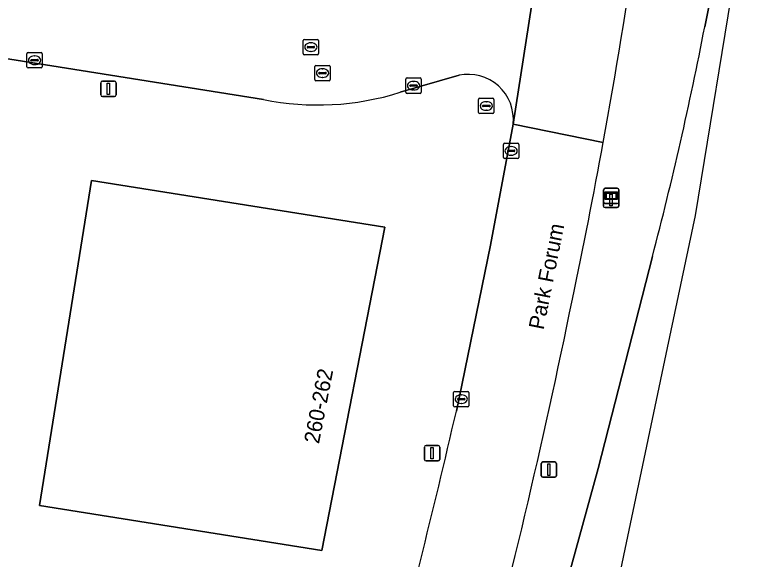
# Model space of a CAD drawing. Extents: x 154324 to 155744, y 382937 to 384188.
# Drawn here: x 155344.13 to 155393.14, y 383264.28 to 383299.76 of the extents above; entities that cross this region are included whole.
import ezdxf

# ---------------------------------------------------------------- set-up
doc = ezdxf.new("R2010")
doc.units = 0
for name, color, linetype in [('IMGEO_Berm_groen', 7, 'Continuous'), ('IMGEO_Brandkraan', 7, 'Continuous'), ('IMGEO_Erf', 7, 'Continuous'), ('IMGEO_Fietspad_gesloten', 7, 'Continuous'), ('IMGEO_Kolk', 7, 'Continuous'), ('IMGEO_Lichtmast', 7, 'Continuous'), ('IMGEO_Openbare_ruimte_label', 7, 'Continuous'), ('IMGEO_Pand', 7, 'Continuous'), ('IMGEO_Pand_nummerreeks', 7, 'Continuous'), ('IMGEO_Rijbaan_lokaal_gesloten', 7, 'Continuous'), ('IMGEO_Rijbaan_lokaal_open', 7, 'Continuous'), ('IMGEO_Rioolput', 7, 'Continuous'), ('IMGEO_Verklikker', 7, 'Continuous')]:
    doc.layers.add(name, color=color, linetype=linetype)

msp = doc.modelspace()

# ---------------------------------------------------------------- linework, layer by layer
at = {"layer": 'IMGEO_Berm_groen'}
for points in [[(155389.025, 383298.986), (155392.104, 383314.484)], [(155378.211, 383256.107), (155382.092, 383270.232), (155385.619, 383284.035)]]:
    msp.add_lwpolyline(points, dxfattribs=at)
for centre, radius, start, end in [((155001.57, 383361.032), 387.149, 349.64863, 353.73096), ((155162.148, 383342.808), 231.07, 345.26497, 349.06787), ((155004.637, 383360.399), 384.018, 348.10768, 349.65929), ((154920.161, 383375.05), 469.711, 344.96734, 348.48239)]:
    msp.add_arc(centre, radius, start, end, dxfattribs=at)
at = {"layer": 'IMGEO_Brandkraan'}
for p, q in [((155374.307, 383293.413), (155374.307, 383294.265)), ((155374.382, 383294.339), (155375.234, 383294.339)), ((155375.308, 383294.265), (155375.308, 383293.413)), ((155374.566, 383293.833), (155374.566, 383293.845)), ((155375.004, 383293.796), (155374.606, 383293.796)), ((155374.609, 383293.882), (155375.007, 383293.882)), ((155374.795, 383294.119), (155374.82, 383294.119)), ((155375.05, 383293.845), (155375.05, 383293.833)), ((155375.234, 383293.339), (155374.382, 383293.339)), ((155374.818, 383293.559), (155374.793, 383293.559))]:
    msp.add_line(p, q, dxfattribs=at)
for points in [[(155374.307, 383293.413), (155374.307, 383294.265)], [(155374.382, 383294.339), (155375.234, 383294.339)], [(155375.308, 383294.265), (155375.308, 383293.413)], [(155375.234, 383293.339), (155374.382, 383293.339)]]:
    msp.add_lwpolyline(points, dxfattribs=at)
for centre, radius, start, end in [((155374.384, 383294.263), 0.0765, 91.552, 178.448), ((155374.384, 383294.263), 0.0765, 91.552, 178.448), ((155375.232, 383294.263), 0.0765, 1.552, 88.448), ((155375.232, 383294.263), 0.0765, 1.552, 88.448), ((155374.606, 383293.842), 0.0403, 85.8775, 175.7526), ((155374.603, 383293.832), 0.0366, 178.938, 274.7102), ((155375.007, 383293.839), 0.043, 264.8664, 352.4533), ((155375.011, 383293.844), 0.0386, 1.7309, 96.639), ((155374.384, 383293.415), 0.0765, 181.552, 268.448), ((155374.384, 383293.415), 0.0765, 181.552, 268.448), ((155375.232, 383293.415), 0.0765, 271.552, 358.448), ((155375.232, 383293.415), 0.0765, 271.552, 358.448)]:
    msp.add_arc(centre, radius, start, end, dxfattribs=at)
for centre, major_axis, ratio, start_param, end_param in [((155374.794, 383293.839), (-0.387, 0.002), 0.722429, 4.712389, 7.853982), ((155374.819, 383293.839), (-0.39, 0.002), 0.717154, 1.570796, 4.712389)]:
    msp.add_ellipse(centre, major_axis=major_axis, ratio=ratio, start_param=start_param, end_param=end_param, dxfattribs=at)
at = {"layer": 'IMGEO_Erf'}
for points in [[(155360.296, 383294.263), (155341.319, 383297.286), (155334.487, 383253.554), (155331.676, 383253.994), (155326.27, 383221.771), (155342.552, 383219.211)], [(155373.032, 383295.835), (155369.195, 383294.73)], [(155372.858, 383273.968), (155375.091, 383284.785), (155376.559, 383292.665)]]:
    msp.add_lwpolyline(points, dxfattribs=at)
msp.add_lwpolyline([(155345.718, 383267.835), (155349.104, 383288.993), (155368.192, 383285.952), (155364.094, 383264.892)], close=True, dxfattribs=at)
for centre, radius, start, end in [((155373.627, 383292.95), 2.946, 354.4495, 101.6533), ((155363.845, 383311.656), 17.752, 258.4676, 287.5404), ((154771.317, 383413.289), 617.464, 345.099417, 346.959795)]:
    msp.add_arc(centre, radius, start, end, dxfattribs=at)
at = {"layer": 'IMGEO_Fietspad_gesloten'}
for points in [[(155374.508, 383231.879), (155378.906, 383245.985), (155381.726, 383255.864), (155383.313, 383262.405), (155386.611, 383278.083), (155388.426, 383286.714), (155391.127, 383303.306), (155393.141, 383320.278)], [(155392.104, 383314.484), (155389.025, 383298.986)], [(155385.619, 383284.035), (155382.092, 383270.232), (155378.211, 383256.107)]]:
    msp.add_lwpolyline(points, dxfattribs=at)
msp.add_arc((155162.148, 383342.808), 231.07, 345.26497, 349.06787, dxfattribs=at)
at = {"layer": 'IMGEO_Kolk'}
for p, q in [((155344.904, 383296.389), (155344.904, 383297.241)), ((155344.979, 383297.315), (155345.831, 383297.315)), ((155345.905, 383297.241), (155345.905, 383296.389)), ((155345.163, 383296.809), (155345.163, 383296.821)), ((155345.601, 383296.772), (155345.203, 383296.772)), ((155345.206, 383296.858), (155345.604, 383296.858)), ((155345.392, 383297.095), (155345.417, 383297.095)), ((155345.647, 383296.821), (155345.647, 383296.809)), ((155345.831, 383296.315), (155344.979, 383296.315)), ((155345.415, 383296.535), (155345.39, 383296.535)), ((155369.571, 383294.736), (155369.571, 383295.588)), ((155369.646, 383295.662), (155370.498, 383295.662)), ((155370.059, 383295.442), (155370.084, 383295.442)), ((155370.572, 383295.588), (155370.572, 383294.736)), ((155369.83, 383295.156), (155369.83, 383295.168)), ((155370.268, 383295.119), (155369.87, 383295.119)), ((155369.873, 383295.205), (155370.271, 383295.205)), ((155370.082, 383294.882), (155370.057, 383294.882)), ((155370.314, 383295.168), (155370.314, 383295.156)), ((155370.498, 383294.662), (155369.646, 383294.662)), ((155375.919, 383290.489), (155375.919, 383291.341)), ((155375.994, 383291.415), (155376.846, 383291.415)), ((155376.92, 383291.341), (155376.92, 383290.489)), ((155376.178, 383290.909), (155376.178, 383290.921)), ((155376.616, 383290.872), (155376.218, 383290.872)), ((155376.221, 383290.958), (155376.619, 383290.958)), ((155376.407, 383291.195), (155376.432, 383291.195)), ((155376.662, 383290.921), (155376.662, 383290.909)), ((155376.846, 383290.415), (155375.994, 383290.415)), ((155376.43, 383290.635), (155376.405, 383290.635)), ((155372.679, 383274.325), (155372.679, 383275.177)), ((155372.754, 383275.251), (155373.606, 383275.251)), ((155373.68, 383275.177), (155373.68, 383274.325)), ((155372.938, 383274.745), (155372.938, 383274.757)), ((155373.376, 383274.708), (155372.978, 383274.708)), ((155372.981, 383274.794), (155373.379, 383274.794)), ((155373.167, 383275.031), (155373.192, 383275.031)), ((155373.422, 383274.757), (155373.422, 383274.745)), ((155373.606, 383274.251), (155372.754, 383274.251)), ((155373.19, 383274.471), (155373.165, 383274.471))]:
    msp.add_line(p, q, dxfattribs=at)
for points in [[(155344.904, 383296.389), (155344.904, 383297.241)], [(155344.979, 383297.315), (155345.831, 383297.315)], [(155345.905, 383297.241), (155345.905, 383296.389)], [(155345.831, 383296.315), (155344.979, 383296.315)], [(155369.571, 383294.736), (155369.571, 383295.588)], [(155369.646, 383295.662), (155370.498, 383295.662)], [(155370.572, 383295.588), (155370.572, 383294.736)], [(155370.498, 383294.662), (155369.646, 383294.662)], [(155375.919, 383290.489), (155375.919, 383291.341)], [(155375.994, 383291.415), (155376.846, 383291.415)], [(155376.92, 383291.341), (155376.92, 383290.489)], [(155376.846, 383290.415), (155375.994, 383290.415)], [(155372.679, 383274.325), (155372.679, 383275.177)], [(155372.754, 383275.251), (155373.606, 383275.251)], [(155373.68, 383275.177), (155373.68, 383274.325)], [(155373.606, 383274.251), (155372.754, 383274.251)]]:
    msp.add_lwpolyline(points, dxfattribs=at)
for centre, radius, start, end in [((155344.981, 383297.239), 0.0765, 91.552, 178.448), ((155344.981, 383297.239), 0.0765, 91.552, 178.448), ((155345.829, 383297.239), 0.0765, 1.552, 88.448), ((155345.829, 383297.239), 0.0765, 1.552, 88.448), ((155345.203, 383296.818), 0.0403, 85.8775, 175.7526), ((155345.2, 383296.808), 0.0366, 178.938, 274.7102), ((155345.604, 383296.815), 0.043, 264.8664, 352.4533), ((155345.608, 383296.82), 0.0386, 1.7309, 96.639), ((155344.981, 383296.391), 0.0765, 181.552, 268.448), ((155344.981, 383296.391), 0.0765, 181.552, 268.448), ((155345.829, 383296.391), 0.0765, 271.552, 358.448), ((155345.829, 383296.391), 0.0765, 271.552, 358.448), ((155369.648, 383295.586), 0.0765, 91.552, 178.448), ((155369.648, 383295.586), 0.0765, 91.552, 178.448), ((155370.496, 383295.586), 0.0765, 1.552, 88.448), ((155370.496, 383295.586), 0.0765, 1.552, 88.448), ((155369.648, 383294.738), 0.0765, 181.552, 268.448), ((155369.648, 383294.738), 0.0765, 181.552, 268.448), ((155369.87, 383295.165), 0.0403, 85.8775, 175.7526), ((155369.867, 383295.155), 0.0366, 178.938, 274.7102), ((155370.271, 383295.162), 0.043, 264.8664, 352.4533), ((155370.275, 383295.167), 0.0386, 1.7309, 96.639), ((155370.496, 383294.738), 0.0765, 271.552, 358.448), ((155370.496, 383294.738), 0.0765, 271.552, 358.448), ((155375.996, 383291.339), 0.0765, 91.552, 178.448), ((155375.996, 383291.339), 0.0765, 91.552, 178.448), ((155376.844, 383291.339), 0.0765, 1.552, 88.448), ((155376.844, 383291.339), 0.0765, 1.552, 88.448), ((155376.218, 383290.918), 0.0403, 85.8775, 175.7526), ((155376.215, 383290.908), 0.0366, 178.938, 274.7102), ((155376.619, 383290.915), 0.043, 264.8664, 352.4533), ((155376.623, 383290.92), 0.0386, 1.7309, 96.639), ((155375.996, 383290.491), 0.0765, 181.552, 268.448), ((155375.996, 383290.491), 0.0765, 181.552, 268.448), ((155376.844, 383290.491), 0.0765, 271.552, 358.448), ((155376.844, 383290.491), 0.0765, 271.552, 358.448), ((155372.756, 383275.175), 0.0765, 91.552, 178.448), ((155372.756, 383275.175), 0.0765, 91.552, 178.448), ((155373.604, 383275.175), 0.0765, 1.552, 88.448), ((155373.604, 383275.175), 0.0765, 1.552, 88.448), ((155372.978, 383274.754), 0.0403, 85.8775, 175.7526), ((155372.975, 383274.744), 0.0366, 178.938, 274.7102), ((155373.379, 383274.751), 0.043, 264.8664, 352.4533), ((155373.383, 383274.756), 0.0386, 1.7309, 96.639), ((155372.756, 383274.327), 0.0765, 181.552, 268.448), ((155372.756, 383274.327), 0.0765, 181.552, 268.448), ((155373.604, 383274.327), 0.0765, 271.552, 358.448), ((155373.604, 383274.327), 0.0765, 271.552, 358.448)]:
    msp.add_arc(centre, radius, start, end, dxfattribs=at)
for centre, major_axis, ratio, start_param, end_param in [((155345.391, 383296.815), (-0.387, 0.002), 0.722429, 4.712389, 7.853982), ((155345.416, 383296.815), (-0.39, 0.002), 0.717154, 1.570796, 4.712389), ((155370.058, 383295.162), (-0.387, 0.002), 0.722429, 4.712389, 7.853982), ((155370.083, 383295.162), (-0.39, 0.002), 0.717154, 1.570796, 4.712389), ((155376.406, 383290.915), (-0.387, 0.002), 0.722429, 4.712389, 7.853982), ((155376.431, 383290.915), (-0.39, 0.002), 0.717154, 1.570796, 4.712389), ((155373.166, 383274.751), (-0.387, 0.002), 0.722429, 4.712389, 7.853982), ((155373.191, 383274.751), (-0.39, 0.002), 0.717154, 1.570796, 4.712389)]:
    msp.add_ellipse(centre, major_axis=major_axis, ratio=ratio, start_param=start_param, end_param=end_param, dxfattribs=at)
at = {"layer": 'IMGEO_Lichtmast'}
for p, q in [((155349.716, 383294.555), (155349.716, 383295.355)), ((155349.716, 383295.355), (155349.716, 383294.555)), ((155349.816, 383295.455), (155350.606, 383295.455)), ((155350.606, 383295.455), (155349.816, 383295.455)), ((155350.706, 383295.355), (155350.706, 383294.555)), ((155350.706, 383294.555), (155350.706, 383295.355)), ((155350.606, 383294.455), (155349.816, 383294.455)), ((155349.816, 383294.455), (155350.606, 383294.455)), ((155382.438, 383287.323), (155382.438, 383288.123)), ((155382.438, 383288.123), (155382.438, 383287.323)), ((155382.538, 383288.223), (155383.328, 383288.223)), ((155383.328, 383288.223), (155382.538, 383288.223)), ((155383.428, 383288.123), (155383.428, 383287.323)), ((155383.428, 383287.323), (155383.428, 383288.123)), ((155383.328, 383287.223), (155382.538, 383287.223)), ((155382.538, 383287.223), (155383.328, 383287.223)), ((155370.883, 383271.731), (155371.673, 383271.731)), ((155371.673, 383271.731), (155370.883, 383271.731)), ((155370.783, 383270.831), (155370.783, 383271.631)), ((155370.783, 383271.631), (155370.783, 383270.831)), ((155371.773, 383271.631), (155371.773, 383270.831)), ((155371.773, 383270.831), (155371.773, 383271.631)), ((155371.673, 383270.731), (155370.883, 383270.731)), ((155370.883, 383270.731), (155371.673, 383270.731)), ((155378.383, 383269.765), (155378.383, 383270.565)), ((155378.383, 383270.565), (155378.383, 383269.765)), ((155378.483, 383270.665), (155379.273, 383270.665)), ((155379.273, 383270.665), (155378.483, 383270.665)), ((155379.373, 383270.565), (155379.373, 383269.765)), ((155379.373, 383269.765), (155379.373, 383270.565)), ((155379.273, 383269.665), (155378.483, 383269.665)), ((155378.483, 383269.665), (155379.273, 383269.665))]:
    msp.add_line(p, q, dxfattribs=at)
for points in [[(155350.136, 383295.33), (155350.286, 383295.33), (155350.286, 383294.58), (155350.136, 383294.58), (155350.136, 383295.33)], [(155382.858, 383288.098), (155383.008, 383288.098), (155383.008, 383287.348), (155382.858, 383287.348), (155382.858, 383288.098)], [(155371.203, 383271.606), (155371.353, 383271.606), (155371.353, 383270.856), (155371.203, 383270.856), (155371.203, 383271.606)], [(155378.803, 383270.54), (155378.953, 383270.54), (155378.953, 383269.79), (155378.803, 383269.79), (155378.803, 383270.54)]]:
    msp.add_lwpolyline(points, dxfattribs=at)
for centre, start, end in [((155349.816, 383295.355), 90, 180), ((155349.816, 383295.355), 90, 180), ((155350.606, 383295.355), 0, 90), ((155350.606, 383295.355), 360, 90), ((155349.816, 383294.555), 180, 270), ((155349.816, 383294.555), 180, 270), ((155350.606, 383294.555), 270, 0), ((155350.606, 383294.555), 270, 0), ((155382.538, 383288.123), 90, 180), ((155382.538, 383288.123), 90, 180), ((155383.328, 383288.123), 0, 90), ((155383.328, 383288.123), 360, 90), ((155382.538, 383287.323), 180, 270), ((155382.538, 383287.323), 180, 270), ((155383.328, 383287.323), 270, 0), ((155383.328, 383287.323), 270, 0), ((155370.883, 383271.631), 90, 180), ((155370.883, 383271.631), 90, 180), ((155371.673, 383271.631), 0, 90), ((155371.673, 383271.631), 360, 90), ((155370.883, 383270.831), 180, 270), ((155370.883, 383270.831), 180, 270), ((155371.673, 383270.831), 270, 0), ((155371.673, 383270.831), 270, 0), ((155378.483, 383270.565), 90, 180), ((155378.483, 383270.565), 90, 180), ((155379.273, 383270.565), 0, 90), ((155379.273, 383270.565), 360, 90), ((155378.483, 383269.765), 180, 270), ((155378.483, 383269.765), 180, 270), ((155379.273, 383269.765), 270, 0), ((155379.273, 383269.765), 270, 0)]:
    msp.add_arc(centre, 0.1, start, end, dxfattribs=at)
at = {"layer": 'IMGEO_Pand'}
msp.add_lwpolyline([(155368.192, 383285.952), (155349.104, 383288.993), (155345.718, 383267.835), (155364.094, 383264.892)], close=True, dxfattribs=at)
at = {"layer": 'IMGEO_Rijbaan_lokaal_gesloten'}
msp.add_lwpolyline([(155382.418, 383291.467), (155376.559, 383292.665), (155375.091, 383284.785), (155372.858, 383273.968)], dxfattribs=at)
for centre, radius, start, end in [((155004.637, 383360.399), 384.018, 348.10768, 349.65929), ((154920.161, 383375.05), 469.711, 344.96734, 348.48239), ((154771.317, 383413.289), 617.464, 345.099417, 346.959795)]:
    msp.add_arc(centre, radius, start, end, dxfattribs=at)
at = {"layer": 'IMGEO_Rijbaan_lokaal_open'}
for points in [[(155214.765, 383317.447), (155341.319, 383297.286), (155360.296, 383294.263)], [(155379.953, 383314.794), (155379.78, 383313.49), (155376.559, 383292.665), (155382.418, 383291.467)], [(155376.559, 383292.665), (155379.78, 383313.49)], [(155369.195, 383294.73), (155373.032, 383295.835)]]:
    msp.add_lwpolyline(points, dxfattribs=at)
for centre, radius, start, end in [((155001.57, 383361.032), 387.149, 349.64863, 353.73096), ((155373.627, 383292.95), 2.946, 354.4495, 101.6533), ((155363.845, 383311.656), 17.752, 258.4676, 287.5404)]:
    msp.add_arc(centre, radius, start, end, dxfattribs=at)
at = {"layer": 'IMGEO_Rioolput'}
for p, q in [((155362.963, 383298.173), (155363.815, 383298.173)), ((155362.888, 383297.247), (155362.888, 383298.099)), ((155363.147, 383297.667), (155363.147, 383297.679)), ((155363.19, 383297.716), (155363.588, 383297.716)), ((155363.376, 383297.953), (155363.401, 383297.953)), ((155363.631, 383297.679), (155363.631, 383297.667)), ((155363.889, 383298.099), (155363.889, 383297.247)), ((155363.815, 383297.173), (155362.963, 383297.173)), ((155363.585, 383297.63), (155363.187, 383297.63)), ((155363.399, 383297.393), (155363.374, 383297.393)), ((155363.646, 383295.556), (155363.646, 383296.408)), ((155363.721, 383296.482), (155364.573, 383296.482)), ((155364.134, 383296.262), (155364.159, 383296.262)), ((155364.647, 383296.408), (155364.647, 383295.556)), ((155363.905, 383295.976), (155363.905, 383295.988)), ((155364.343, 383295.939), (155363.945, 383295.939)), ((155363.948, 383296.025), (155364.346, 383296.025)), ((155364.157, 383295.702), (155364.132, 383295.702)), ((155364.389, 383295.988), (155364.389, 383295.976)), ((155364.573, 383295.482), (155363.721, 383295.482))]:
    msp.add_line(p, q, dxfattribs=at)
for points in [[(155362.963, 383298.173), (155363.815, 383298.173)], [(155362.888, 383297.247), (155362.888, 383298.099)], [(155363.889, 383298.099), (155363.889, 383297.247)], [(155363.815, 383297.173), (155362.963, 383297.173)], [(155363.646, 383295.556), (155363.646, 383296.408)], [(155363.721, 383296.482), (155364.573, 383296.482)], [(155364.647, 383296.408), (155364.647, 383295.556)], [(155364.573, 383295.482), (155363.721, 383295.482)]]:
    msp.add_lwpolyline(points, dxfattribs=at)
for centre, radius, start, end in [((155362.965, 383298.097), 0.0765, 91.552, 178.448), ((155362.965, 383298.097), 0.0765, 91.552, 178.448), ((155363.813, 383298.097), 0.0765, 1.552, 88.448), ((155363.813, 383298.097), 0.0765, 1.552, 88.448), ((155363.187, 383297.676), 0.0403, 85.8775, 175.7526), ((155363.184, 383297.666), 0.0366, 178.938, 274.7102), ((155363.588, 383297.673), 0.043, 264.8664, 352.4533), ((155363.592, 383297.678), 0.0386, 1.7309, 96.639), ((155362.965, 383297.249), 0.0765, 181.552, 268.448), ((155362.965, 383297.249), 0.0765, 181.552, 268.448), ((155363.813, 383297.249), 0.0765, 271.552, 358.448), ((155363.813, 383297.249), 0.0765, 271.552, 358.448), ((155363.723, 383296.406), 0.0765, 91.552, 178.448), ((155363.723, 383296.406), 0.0765, 91.552, 178.448), ((155364.571, 383296.406), 0.0765, 1.552, 88.448), ((155364.571, 383296.406), 0.0765, 1.552, 88.448), ((155363.945, 383295.985), 0.0403, 85.8775, 175.7526), ((155363.942, 383295.975), 0.0366, 178.938, 274.7102), ((155364.346, 383295.982), 0.043, 264.8664, 352.4533), ((155364.35, 383295.987), 0.0386, 1.7309, 96.639), ((155363.723, 383295.558), 0.0765, 181.552, 268.448), ((155363.723, 383295.558), 0.0765, 181.552, 268.448), ((155364.571, 383295.558), 0.0765, 271.552, 358.448), ((155364.571, 383295.558), 0.0765, 271.552, 358.448)]:
    msp.add_arc(centre, radius, start, end, dxfattribs=at)
for centre, major_axis, ratio, start_param, end_param in [((155363.375, 383297.673), (-0.387, 0.002), 0.722429, 4.712389, 7.853982), ((155363.4, 383297.673), (-0.39, 0.002), 0.717154, 1.570796, 4.712389), ((155364.133, 383295.982), (-0.387, 0.002), 0.722429, 4.712389, 7.853982), ((155364.158, 383295.982), (-0.39, 0.002), 0.717154, 1.570796, 4.712389)]:
    msp.add_ellipse(centre, major_axis=major_axis, ratio=ratio, start_param=start_param, end_param=end_param, dxfattribs=at)
at = {"layer": 'IMGEO_Verklikker'}
for p, q in [((155382.444, 383287.579), (155382.444, 383288.379)), ((155382.444, 383288.379), (155382.444, 383287.579)), ((155382.544, 383288.479), (155383.334, 383288.479)), ((155383.334, 383288.479), (155382.544, 383288.479)), ((155383.434, 383288.379), (155383.434, 383287.579)), ((155383.434, 383287.579), (155383.434, 383288.379)), ((155383.334, 383287.479), (155382.544, 383287.479)), ((155382.544, 383287.479), (155383.334, 383287.479))]:
    msp.add_line(p, q, dxfattribs=at)
for points in [[(155382.545, 383288.211), (155383.333, 383288.211), (155383.333, 383287.747), (155382.545, 383287.747), (155382.545, 383288.211)], [(155382.61, 383288.146), (155382.61, 383287.812), (155383.268, 383287.812), (155383.268, 383288.146), (155382.61, 383288.146)]]:
    msp.add_lwpolyline(points, dxfattribs=at)
for centre, start, end in [((155382.544, 383288.379), 90, 180), ((155382.544, 383288.379), 90, 180), ((155383.334, 383288.379), 0, 90), ((155383.334, 383288.379), 360, 90), ((155382.544, 383287.579), 180, 270), ((155382.544, 383287.579), 180, 270), ((155383.334, 383287.579), 270, 0), ((155383.334, 383287.579), 270, 0)]:
    msp.add_arc(centre, 0.1, start, end, dxfattribs=at)

# ---------------------------------------------------------------- texts
at = {"layer": 'IMGEO_Openbare_ruimte_label'}
msp.add_text('Park Forum', height=1, rotation=78.8137, dxfattribs=at).set_placement((155378.534, 383279.224))
at = {"layer": 'IMGEO_Pand_nummerreeks'}
msp.add_text('260-262', height=1, rotation=78.988, dxfattribs=at).set_placement((155363.911, 383271.804))

doc.saveas('drawing.dxf')
